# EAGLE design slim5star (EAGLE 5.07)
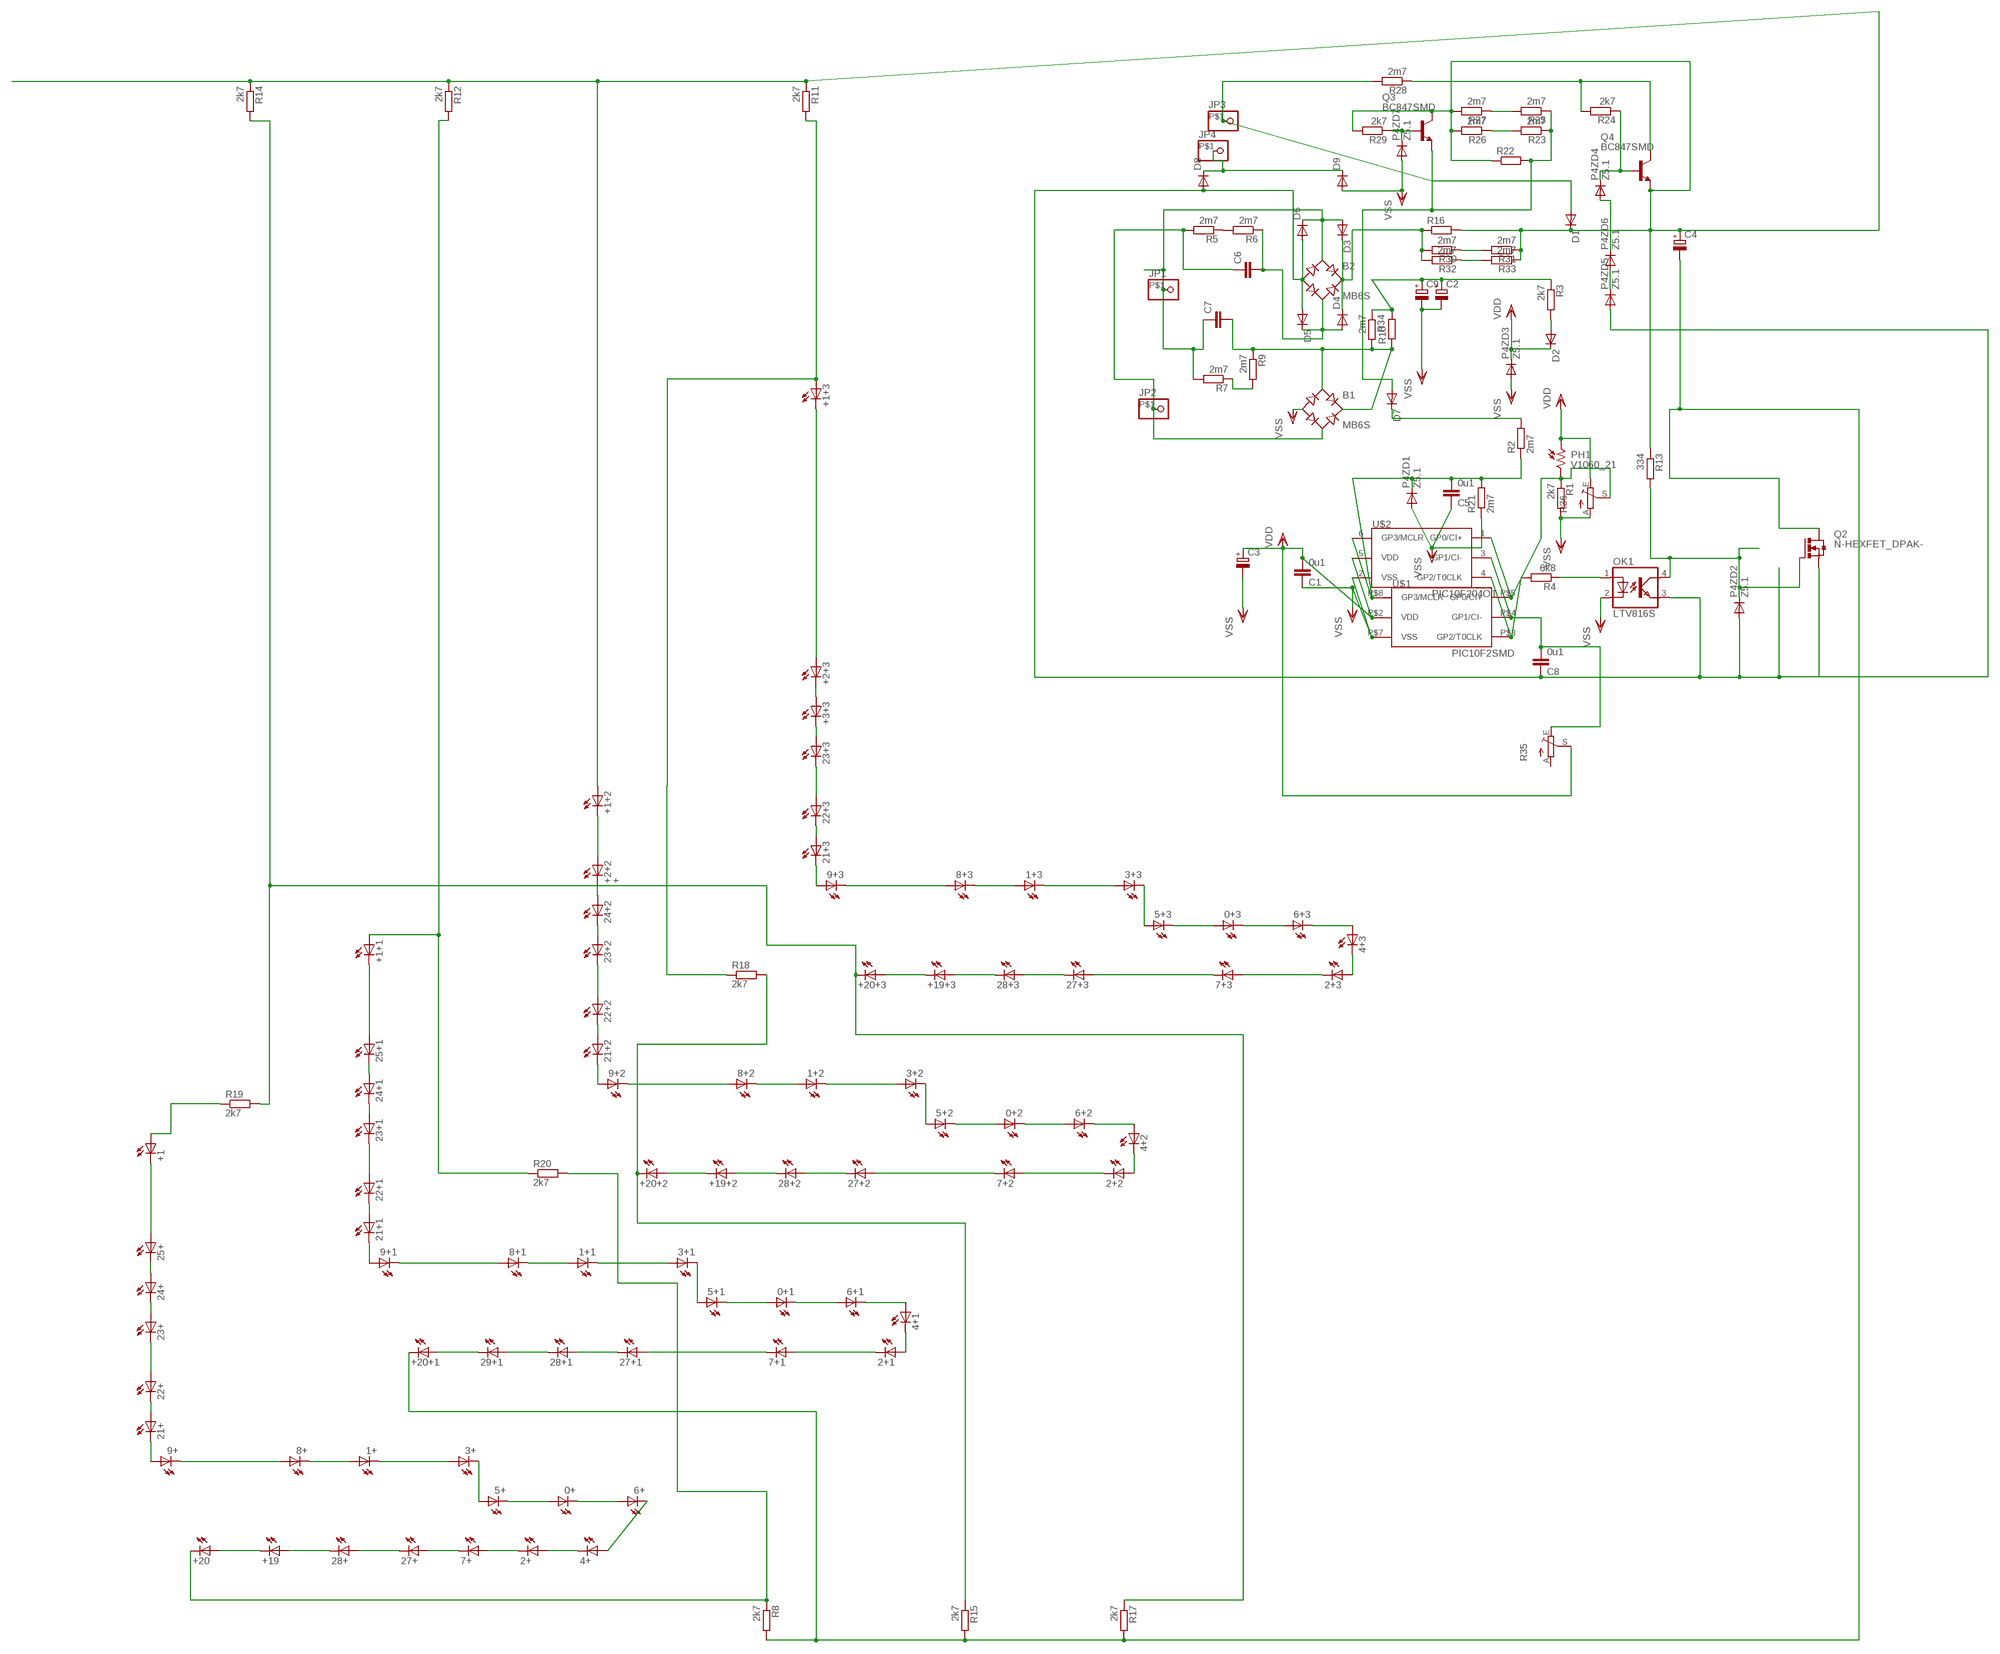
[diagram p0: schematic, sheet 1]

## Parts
0+  LED1210  [1210]
0+1  LED1210  [1210]
0+2  LED1210  [1210]
0+3  LED1210  [1210]
1+  LED1210  [1210]
1+1  LED1210  [1210]
1+2  LED1210  [1210]
1+3  LED1210  [1210]
2+  LED1210  [1210]
2+1  LED1210  [1210]
2+2  LED1210  [1210]
2+3  LED1210  [1210]
3+  LED1210  [1210]
3+1  LED1210  [1210]
3+2  LED1210  [1210]
3+3  LED1210  [1210]
4+  LED1210  [1210]
4+1  LED1210  [1210]
4+2  LED1210  [1210]
4+3  LED1210  [1210]
5+  LED1210  [1210]
5+1  LED1210  [1210]
5+2  LED1210  [1210]
5+3  LED1210  [1210]
6+  LED1210  [1210]
6+1  LED1210  [1210]
6+2  LED1210  [1210]
6+3  LED1210  [1210]
7+  LED1210  [1210]
7+1  LED1210  [1210]
7+2  LED1210  [1210]
7+3  LED1210  [1210]
8+  LED1210  [1210]
8+1  LED1210  [1210]
8+2  LED1210  [1210]
8+3  LED1210  [1210]
9+  LED1210  [1210]
9+1  LED1210  [1210]
9+2  LED1210  [1210]
9+3  LED1210  [1210]
21+  LED1210  [1210]
21+1  LED1210  [1210]
21+2  LED1210  [1210]
21+3  LED1210  [1210]
22+  LED1210  [1210]
22+1  LED1210  [1210]
22+2  LED1210  [1210]
22+3  LED1210  [1210]
23+  LED1210  [1210]
23+1  LED1210  [1210]
23+2  LED1210  [1210]
23+3  LED1210  [1210]
24+  LED1210  [1210]
24+1  LED1210  [1210]
24+2  LED1210  [1210]
25+  LED1210  [1210]
25+1  LED1210  [1210]
27+  LED1210  [1210]
27+1  LED1210  [1210]
27+2  LED1210  [1210]
27+3  LED1210  [1210]
28+  LED1210  [1210]
28+1  LED1210  [1210]
28+2  LED1210  [1210]
28+3  LED1210  [1210]
29+1  LED1210  [1210]
+1  LED1210  [1210]
+1+1  LED1210  [1210]
+1+2  LED1210  [1210]
+1+3  LED1210  [1210]
+2+2  +  LED1210  [1210]
+2+3  LED1210  [1210]
+3+3  LED1210  [1210]
+19  LED1210  [1210]
+19+2  LED1210  [1210]
+19+3  LED1210  [1210]
+20  LED1210  [1210]
+20+1  LED1210  [1210]
+20+2  LED1210  [1210]
+20+3  LED1210  [1210]
B1  MB6S  [SOIC-4]
B2  MB6S  [SOIC-4]
C1  0u1  C-EUC1206  [C1206]
C2  CPOL-EUE2.5-4V  [E2,5RE]
C3  CPOL-EUE  [PANASONIC_E]
C4  CPOL-EUSANYO_SMD_F12  [SANYO-OSCON_SMD_F12]
C5  0u1  C-EUC1206  [C1206]
C6  C-EUSMD200  [SMD200]
C7  C-EUSMD100  [SMD100]
C8  0u1  C-EUC1206  [C1206]
C9  CPOL-EUE  [PANASONIC_E]
D1  DIODE-SMB  [SMB]
D2  DIODE-MINIMELF  [MINIMELF]
D3  DIODE-SMB  [SMB]
D4  DIODE-SMB  [SMB]
D5  DIODE-SMB  [SMB]
D6  DIODE-SMB  [SMB]
D7  DIODE-MINIMELF  [MINIMELF]
D8  DIODE-SMB  [SMB]
D9  DIODE-SMB  [SMB]
JP1  PINHD-1X1SMD  [SMD1X1]
JP2  PINHD-1X1SMD  [SMD1X1]
JP3  PINHD-1X1SMD  [SMD1X1]
JP4  PINHD-1X1SMD  [SMD1X1]
OK1  LTV816S  [SMD4]
P4ZD1  Z5.1  DIODE-MINIMELF  [MINIMELF]
P4ZD2  Z5.1  DIODE-MINIMELF  [MINIMELF]
P4ZD3  Z5.1  DIODE-MINIMELF  [MINIMELF]
P4ZD4  Z5.1  DIODE-MINIMELF  [MINIMELF]
P4ZD5  Z5.1  DIODE-MINIMELF  [MINIMELF]
P4ZD6  Z5.1  DIODE-MINIMELF  [MINIMELF]
P4ZD7  Z5.1  DIODE-MINIMELF  [MINIMELF]
PH1  V1060_21  [TO-5_V10]
Q2  N-HEXFET_DPAK-  [TO252]
Q3  BC847SMD  [SOT23]
Q4  BC847SMD  [SOT23]
R1  2k7  R-EU_R1206  [R1206]
R2  2m7  R-EU_R1206  [R1206]
R3  2k7  R-EU_R1206  [R1206]
R4  6k8  R-EU_R1206  [R1206]
R5  2m7  R-EU_R1210  [R1210]
R6  2m7  R-EU_R1210  [R1210]
R7  2m7  R-EU_R1210  [R1210]
R8  2k7  R-EU_R0402  [R0402]
R9  2m7  R-EU_R1210  [R1210]
R10  R-EU_SMD15  [SMDCARB15]
R11  2k7  R-EU_R0402  [R0402]
R12  2k7  R-EU_R0402  [R0402]
R13  334  R-EU_R1206  [R1206]
R14  2k7  R-EU_R0402  [R0402]
R15  2k7  R-EU_R0402  [R0402]
R16  R-EU_SMD15  [SMDCARB15]
R17  2k7  R-EU_R0402  [R0402]
R18  2k7  R-EU_R0402  [R0402]
R19  2k7  R-EU_R0402  [R0402]
R20  2k7  R-EU_R0402  [R0402]
R21  2m7  R-EU_R1206  [R1206]
R22  R-EU_SMD15  [SMDCARB15]
R23  2m7  R-EU_R1210  [R1210]
R24  2k7  R-EU_R1206  [R1206]
R25  2m7  R-EU_R1210  [R1210]
R26  2m7  R-EU_R1210  [R1210]
R27  2m7  R-EU_R1210  [R1210]
R28  2m7  R-EU_R1210  [R1210]
R29  2k7  R-EU_R1206  [R1206]
R30  2m7  R-EU_R1210  [R1210]
R31  2m7  R-EU_R1210  [R1210]
R32  2m7  R-EU_R1210  [R1210]
R33  2m7  R-EU_R1210  [R1210]
R34  2m7  R-EU_R1210  [R1210]
R35  TRIM_EU-LI15  [LI15]
R36  TRIM_EU-LI15  [LI15]
U$1  PIC10F2SMD  [DIL8SMD]
U$2  PIC10F204OT  [SOT23-6]

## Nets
AC1: B1.~2(AC2) C6.P$1 JP2.P$1 R5.2
AC2: B2.~1(AC1) C7.P$1 D3.A D6.C JP1.P$1 R7.2
CBIG: B2.~2(AC2) C6.P$2 D4.A D5.C R6.1
CSMALL: D7.A Q3.2(E) R22.P$2 R23.1 R25.1
D+: +1+2.P$1(A) C4.+ D1.C Q3.3(C) Q4.2(E) R11.1 R12.1 R13.1 R14.1 R16.P$2 R22.P$1 R26.2 R27.2 R29.2 R31.1 R33.1
MINUS: +20+1.P$2(C) C4.- Q2.3(D) R8.2 R15.2 R17.2
N$1: +1+3.P$1(A) R11.2 R18.1
N$2: +1+1.P$1(A) R12.2 R20.1
N$4: +1.P$1(A) R19.1
N$5: D7.C R2.2
N$6: 8+.P$1(A) 9+.P$2(C)
N$7: +19.P$2(C) +20.P$1(A)
N$8: 28+.P$2(C) +19.P$1(A)
N$9: 27+.P$2(C) 28+.P$1(A)
N$10: 29+1.P$2(C) +20+1.P$1(A)
N$11: 28+1.P$2(C) 29+1.P$1(A)
N$12: 2+.P$2(C) 7+.P$1(A)
N$13: 7+.P$2(C) 27+.P$1(A)
N$14: 2+.P$1(A) 4+.P$2(C)
N$15: 4+.P$1(A) 6+.P$2(C)
N$16: 0+.P$2(C) 6+.P$1(A)
N$17: 0+.P$1(A) 5+.P$2(C)
N$18: 3+.P$2(C) 5+.P$1(A)
N$19: 1+.P$2(C) 3+.P$1(A)
N$20: 1+.P$1(A) 8+.P$2(C)
N$21: 27+1.P$2(C) 28+1.P$1(A)
N$22: 2+1.P$1(A) 4+1.P$2(C)
N$23: 9+.P$1(A) 21+.P$2(C)
N$24: 21+.P$1(A) 22+.P$2(C)
N$25: 22+.P$1(A) 23+.P$2(C)
N$26: 24+.P$1(A) 25+.P$2(C)
N$27: 25+.P$1(A) +1.P$2(C)
N$28: 23+.P$1(A) 24+.P$2(C)
N$29: 4+1.P$1(A) 6+1.P$2(C)
N$30: 0+1.P$2(C) 6+1.P$1(A)
N$31: 0+1.P$1(A) 5+1.P$2(C)
N$32: 3+1.P$2(C) 5+1.P$1(A)
N$33: 1+1.P$2(C) 3+1.P$1(A)
N$34: 1+1.P$1(A) 8+1.P$2(C)
N$35: 9+1.P$1(A) 21+1.P$2(C)
N$36: 21+1.P$1(A) 22+1.P$2(C)
N$37: 22+1.P$1(A) 23+1.P$2(C)
N$38: 25+1.P$1(A) +1+1.P$2(C)
N$39: 24+1.P$1(A) 25+1.P$2(C)
N$40: 23+1.P$1(A) 24+1.P$2(C)
N$41: 2+1.P$2(C) 7+1.P$1(A)
N$42: 7+1.P$2(C) 27+1.P$1(A)
N$43: 8+1.P$1(A) 9+1.P$2(C)
N$45: +20+3.P$2(C) R14.2 R17.1 R19.2
N$46: +19+2.P$2(C) +20+2.P$1(A)
N$47: 28+2.P$2(C) +19+2.P$1(A)
N$48: 27+2.P$2(C) 28+2.P$1(A)
N$49: 2+2.P$1(A) 4+2.P$2(C)
N$50: 4+2.P$1(A) 6+2.P$2(C)
N$51: 0+2.P$2(C) 6+2.P$1(A)
N$52: 0+2.P$1(A) 5+2.P$2(C)
N$53: 3+2.P$2(C) 5+2.P$1(A)
N$54: 1+2.P$2(C) 3+2.P$1(A)
N$55: 1+2.P$1(A) 8+2.P$2(C)
N$56: 9+2.P$1(A) 21+2.P$2(C)
N$57: 21+2.P$1(A) 22+2.P$2(C)
N$58: 22+2.P$1(A) 23+2.P$2(C)
N$59: +1+2.P$2(C) +2+2.P$1(A)
N$60: 24+2.P$1(A) +2+2.P$2(C)
N$61: 23+2.P$1(A) 24+2.P$2(C)
N$62: 2+2.P$2(C) 7+2.P$1(A)
N$63: 7+2.P$2(C) 27+2.P$1(A)
N$64: 8+2.P$1(A) 9+2.P$2(C)
N$65: +20+2.P$2(C) R15.1 R18.2
N$66: +20.P$2(C) R8.1 R20.2
N$67: +19+3.P$2(C) +20+3.P$1(A)
N$68: 28+3.P$2(C) +19+3.P$1(A)
N$69: 27+3.P$2(C) 28+3.P$1(A)
N$70: 2+3.P$1(A) 4+3.P$2(C)
N$71: 4+3.P$1(A) 6+3.P$2(C)
N$72: 0+3.P$2(C) 6+3.P$1(A)
N$73: 0+3.P$1(A) 5+3.P$2(C)
N$74: 3+3.P$2(C) 5+3.P$1(A)
N$75: 1+3.P$2(C) 3+3.P$1(A)
N$76: 1+3.P$1(A) 8+3.P$2(C)
N$77: 9+3.P$1(A) 21+3.P$2(C)
N$78: 21+3.P$1(A) 22+3.P$2(C)
N$79: 22+3.P$1(A) 23+3.P$2(C)
N$80: +1+3.P$2(C) +2+3.P$1(A)
N$81: +2+3.P$2(C) +3+3.P$1(A)
N$82: 23+3.P$1(A) +3+3.P$2(C)
N$83: 2+3.P$2(C) 7+3.P$1(A)
N$84: 7+3.P$2(C) 27+3.P$1(A)
N$85: 8+3.P$1(A) 9+3.P$2(C)
N$86: C5.2 P4ZD1.C R2.1 R21.2 U$1.P$8(GP3/MCLR) U$2.6(GP3/MCLR)
N$87: OK1.1(A) R4.1
N$88: PH1.2 R1.1 R36.S U$1.P$5(GP0/CI+) U$2.1(GP0/CI+)
N$89: R5.1 R6.2
N$90: R7.1 R9.2
N$91: B2.+ D3.C D4.C R16.P$1 R30.2 R32.2
N$92: D2.A R3.2
N$93: B2.- C8.1 D5.A D6.A D8.A OK1.3(EMIT) P4ZD2.A P4ZD5.A Q2.2(S)
N$94: OK1.4(COL) P4ZD2.C Q2.1(G) R13.2
N$95: R4.2 U$1.P$3(GP2/T0CLK) U$2.4(GP2/T0CLK)
N$96: Q4.3(C) R24.2 R28.1
N$97: P4ZD4.C Q4.1(B) R24.1
N$98: D1.A JP3.P$1 R28.2
N$99: R23.2 R26.1
N$100: R25.2 R27.1
N$101: C2.+ C9.+ R3.1 R10.P$2 R34.1
N$102: C8.2 R35.E U$1.P$4(GP1/CI-) U$2.3(GP1/CI-)
N$103: P4ZD5.C P4ZD6.A
N$104: P4ZD7.C Q3.1(B) R29.1
N$105: P4ZD4.A P4ZD6.C
N$106: D8.C D9.C JP4.P$1
N$107: R30.1 R31.2
N$108: R32.1 R33.2
RECDR+: B1.+ B1.~1(AC1) C7.P$2 R9.1 R10.P$1 R34.2
VDD: C1.2 C3.+ D2.C P4ZD3.C PH1.1 R35.S R36.E U$1.P$2(VDD) U$2.5(VDD)
VSS: B1.- C1.1 C2.- C3.- C5.1 C9.- D9.A OK1.2(C) P4ZD1.A P4ZD3.A P4ZD7.A R1.2 R21.1 R36.A U$1.P$7(VSS) U$2.2(VSS)
Unconnected: R35.A

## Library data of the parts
0+ 0+1-0+3 1+ 1+1-1+3 2+ 2+1-2+3 3+ 3+1-3+3 4+ 4+1-4+3 5+ 5+1-5+3 6+ 6+1-6+3 7+ 7+1-7+3 8+ 8+1-8+3 9+ 9+1-9+3 21+ 21+1-21+3 22+ 22+1-22+3 23+ 23+1-23+3 24+ 24+1 24+2 25+ 25+1 27+ 27+1-27+3 28+ 28+1-28+3 29+1 +1 +1+1-+1+3 +2+2 +2+3 +3+3 +19 +19+2 +19+3 +20 +20+1-+20+3 = led(2):LED: LED
B1 B2 = rectifier:MB*S: Bridge Rectifier Source: http://www.fairchildsemi.com/ds/MB/MB6S.pdf
C1 C5-C8 = rcl:C-EU: CAPACITOR, European symbol
C2-C4 C9 = rcl-2:CPOL-EU: POLARIZED CAPACITOR, European symbol
D1-D9 P4ZD1-P4ZD7 = diode:DIODE-: DIODE
JP1-JP4 = pinhead:PINHD-1X1: PIN HEADER
OK1 = optocoupler:LTV816: OPTO COUPLER Source: LITEON, LTV816.pdf
PH1 = photo-elements:?1060*: Sensor Street Light control
Q2 = transistor-power:N-HEXFET_?-*: HEXFET® Power MOSFET
Q3 Q4 = transistor-npn:BC847*: NPN Transistor
R1-R9 R11-R15 R17-R21 R23-R34 = rcl-2:R-EU_: RESISTOR, European symbol
R10 R16 R22 = rcl:R-EU_: RESISTOR, European symbol
R35 R36 = pot:TRIM_EU-: POTENTIOMETER
U$1 U$2 = microchip-5:PIC10F2*: uPC nW 0,25/0,5k Program Flash memory Comparator

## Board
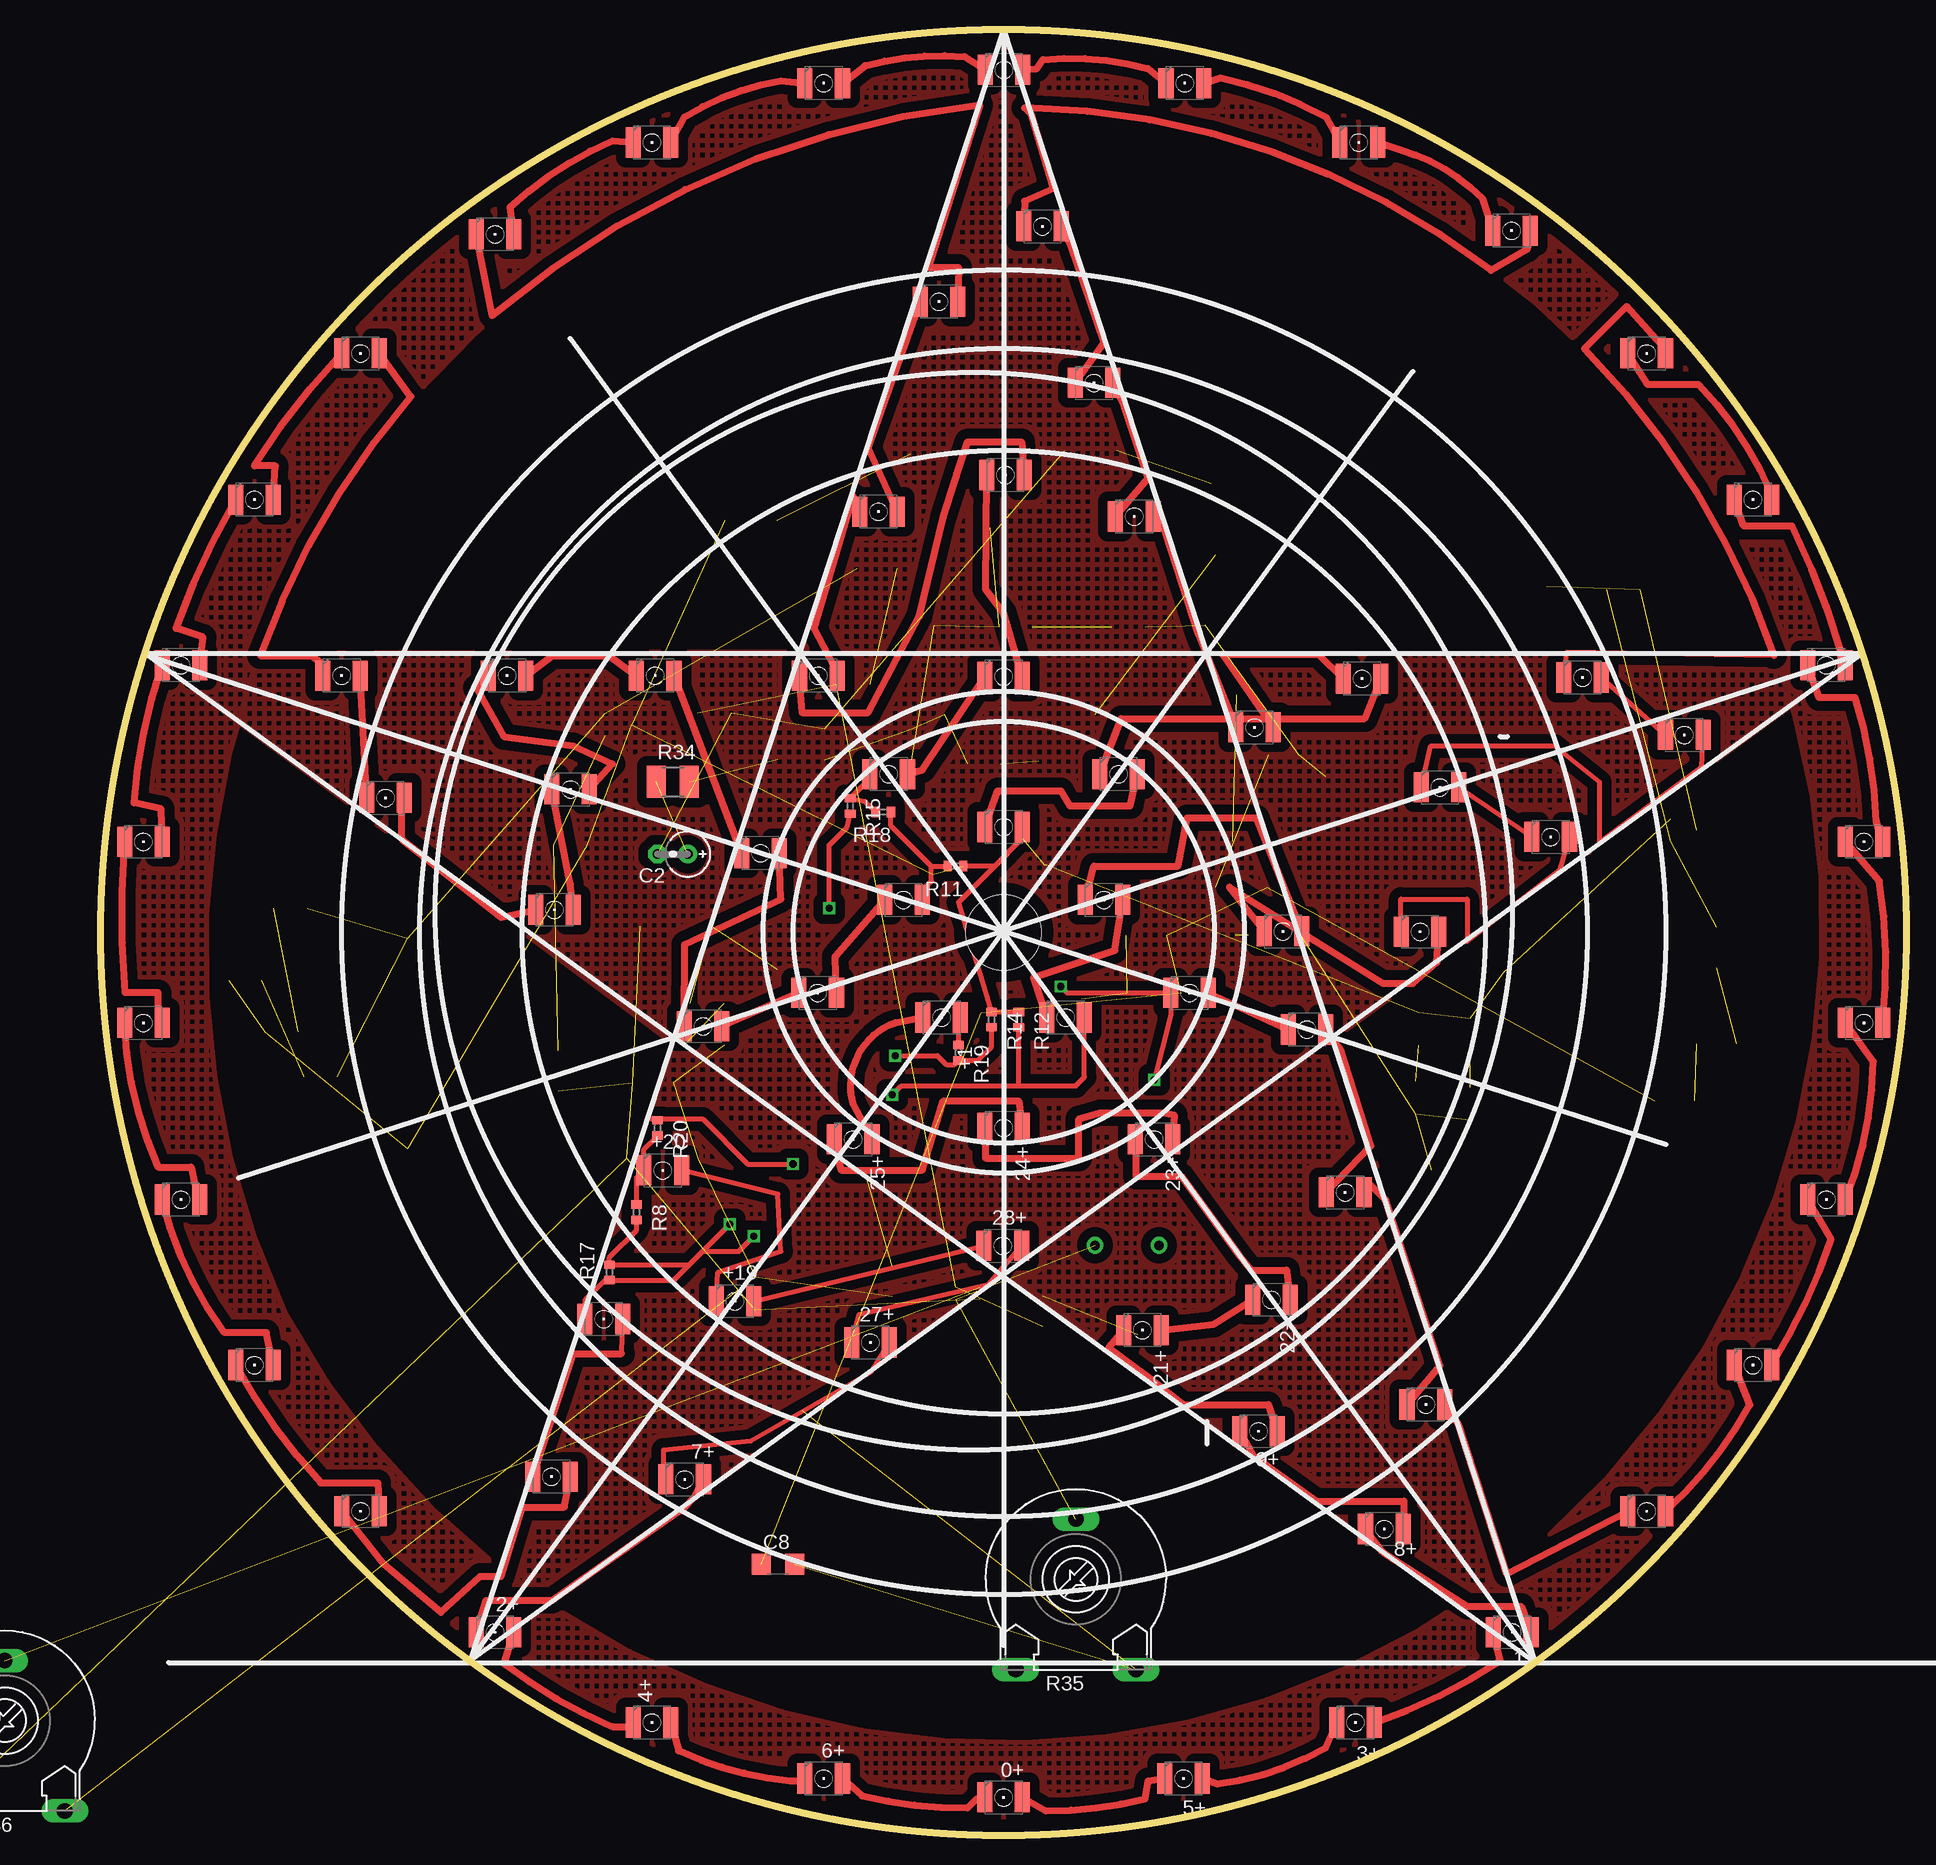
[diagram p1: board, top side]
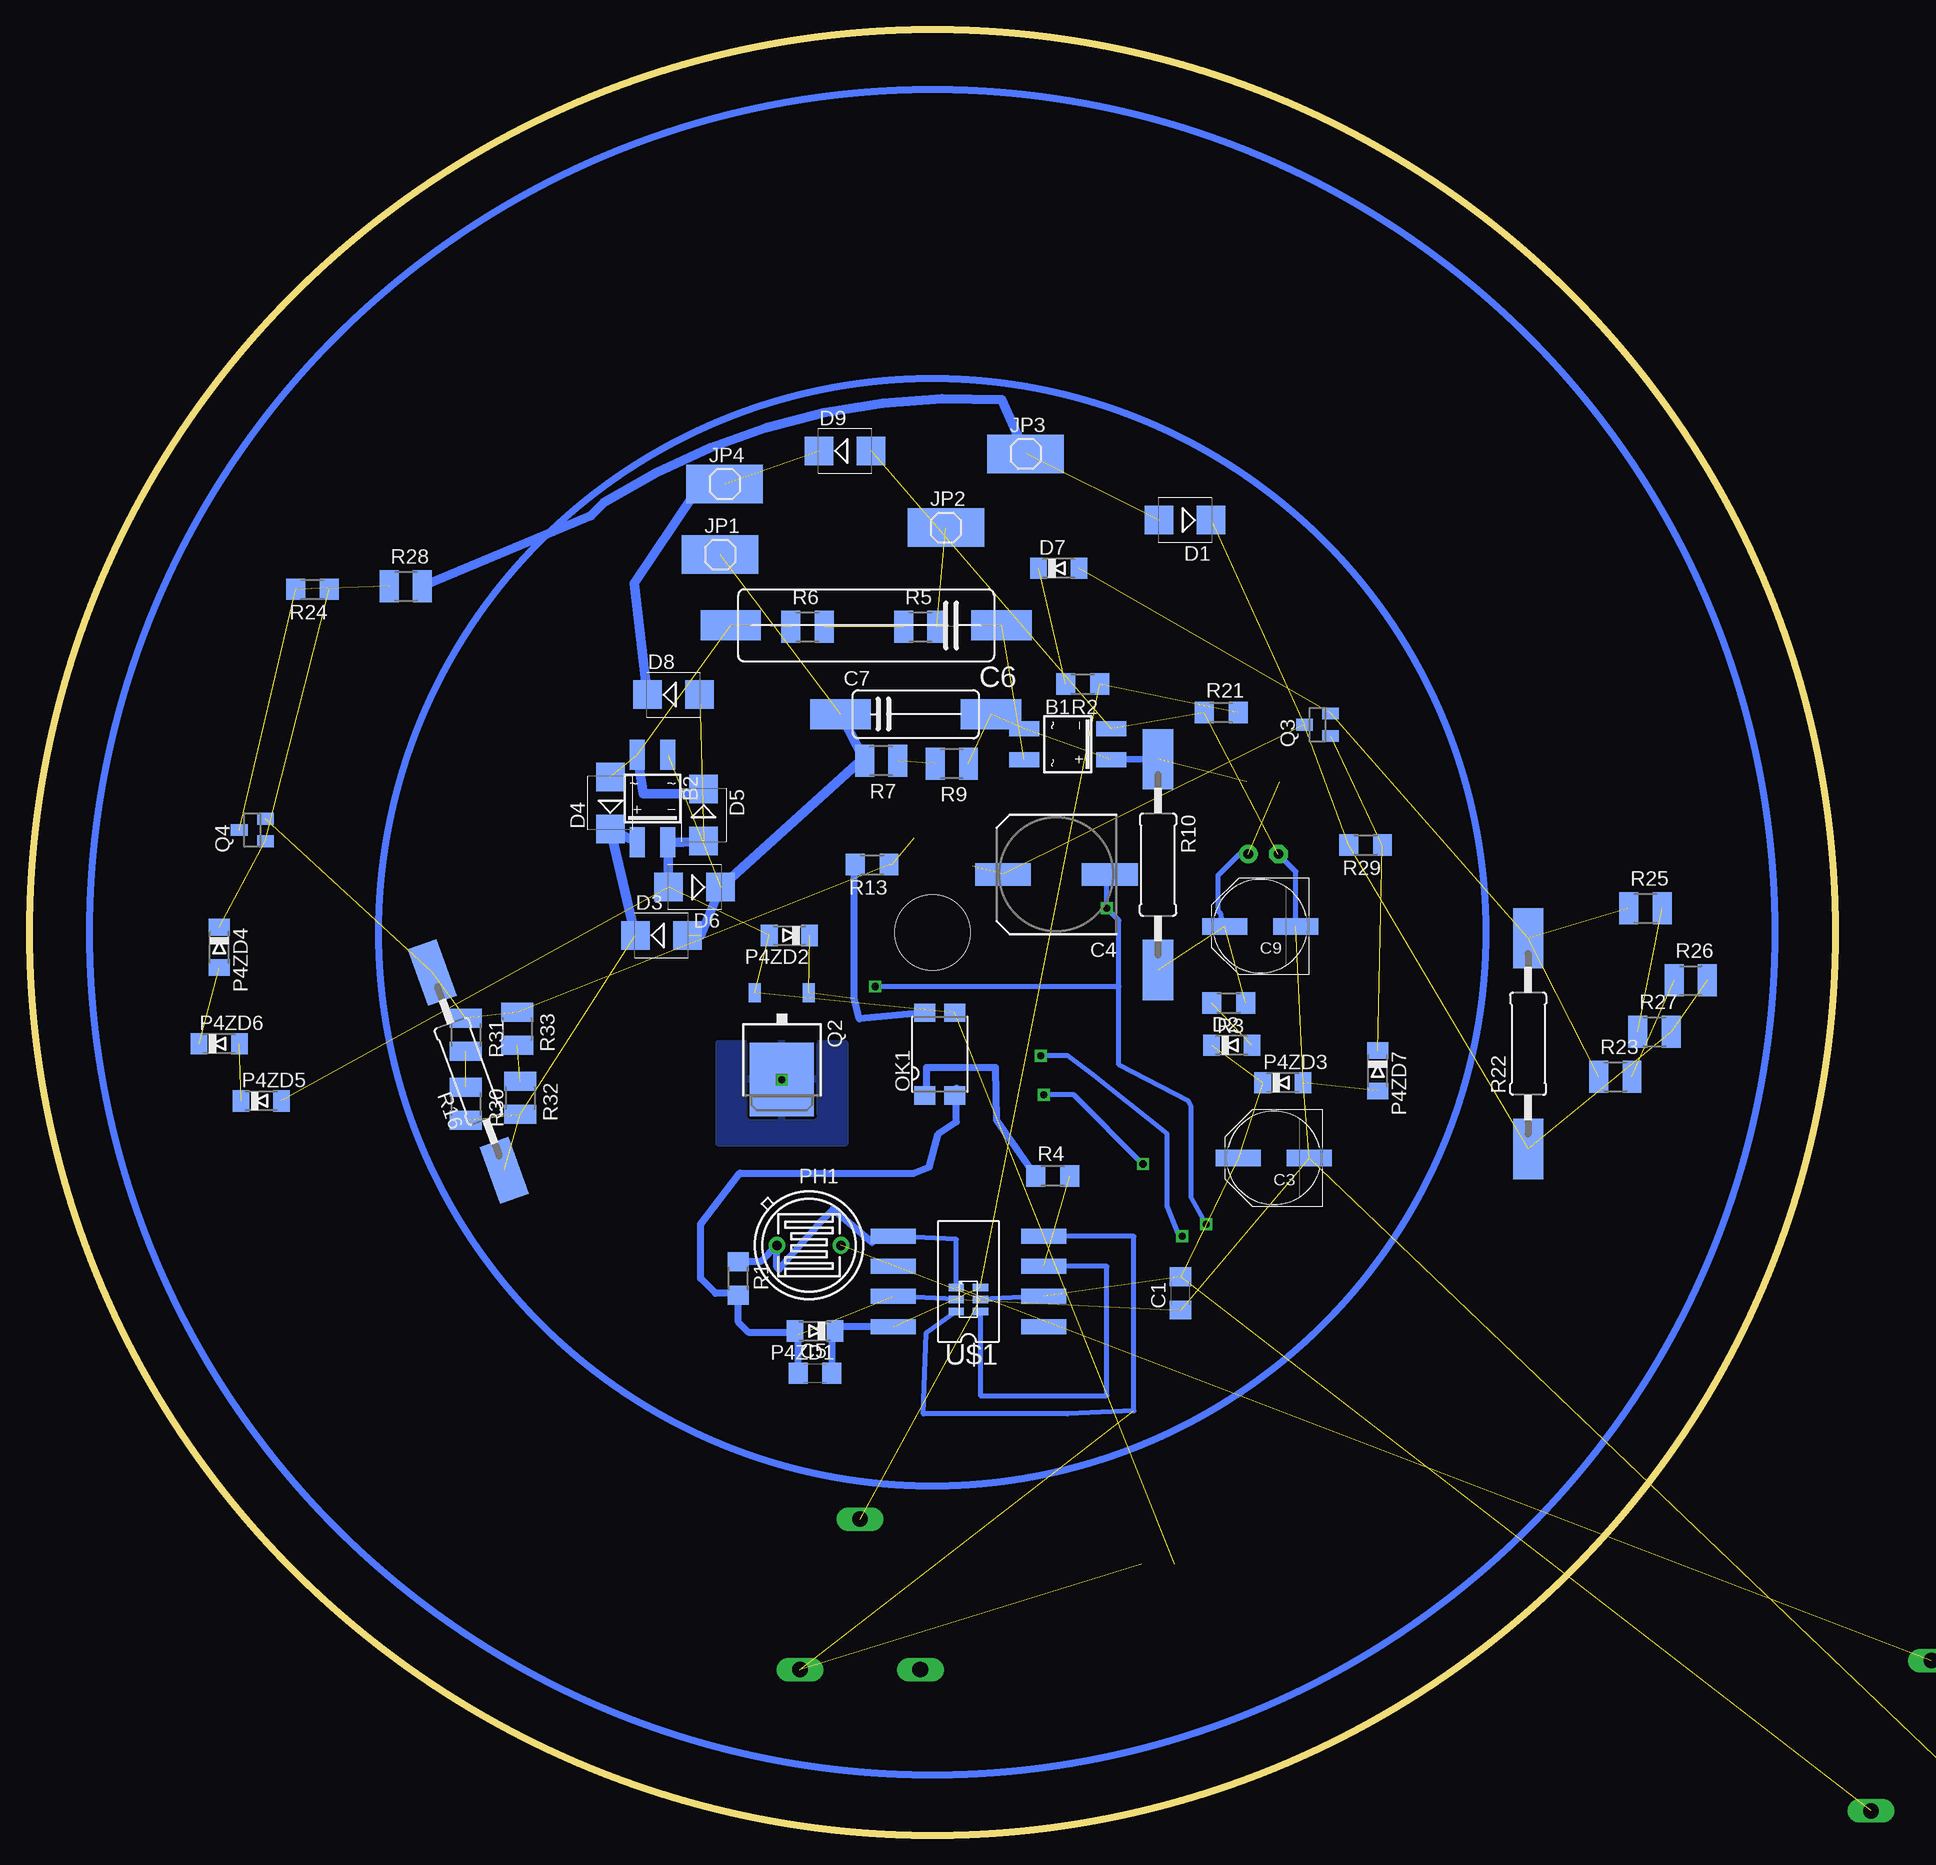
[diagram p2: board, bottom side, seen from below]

Size 152.4 x 152.4 mm. Coordinates in mm from the lower left corner, seen from the top.
Outline: circle at 76.2,76.2 radius 76.2
Copper layers (1*16): Top 0.035mm / dielectric 1.5mm / Bottom 0.035mm
Design rules "default": minimum track width 10mil, minimum drill 24mil, track to track 8mil, track to pad 8mil, pad to pad 8mil, via to via 8mil, smd to smd 8mil, copper to edge 40mil, drill to drill 8mil, minimum pad ring 10mil, minimum via ring 8mil, stop-mask expansion 4mil, vias tented up to drill 0mil, thermal gap 10mil
Holes 6.35 mm at 76.2,76.2

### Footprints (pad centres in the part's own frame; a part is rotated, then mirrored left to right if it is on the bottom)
1210 = smd 1.27 x 2.54: P$1 1.587,0; P$2 -1.587,0
SOIC-4 = smd 1.27 x 2.54: + 1.3,3.685; - -1.3,3.685; ~1 -1.3,-3.685; ~2 1.3,-3.685
C1206 = smd 1.6 x 1.8: 1 -1.4,0; 2 1.4,0
E2,5RE = drill 0.813 pad 1.575 round: + -1.27,0 | drill 0.813 pad 1.575 octagon: - 1.27,0
PANASONIC_E = smd 3.8 x 1.4: + 3,0; - -3,0
SANYO-OSCON_SMD_F12 = smd 4.7 x 1.9: + 4.5,0; - -4.5,0
SMD200 = smd 5.08 x 2.54: P$1 -10.16,0; P$2 12.7,0
SMD100 = smd 5.08 x 2.54: P$1 -6.35,0; P$2 6.35,0
SMB = smd 2.4 x 2.4: A 2.2,0; C -2.2,0
MINIMELF = smd 1.4 x 1.8: A 1.7,0; C -1.7,0
SMD1X1 = smd 6.452 x 3.251: P$1 0,0
SMD4 = smd 1.78 x 1.55: 1 -1.27,-3.5; 2 1.27,-3.5; 3 1.27,3.5; 4 -1.27,3.5
TO-5_V10 = drill 0.8 pad 1.4 round: 1 -2.7,0; 2 2.7,0
TO252 = smd 1 x 1.6: 1 -2.28,-3.53; 2 2.28,-3.53 | smd 5.4 x 6.2: 3 0,3.77
SOT23 = smd 1 x 1.4: 1 -0.95,-1.1; 2 0.95,-1.1; 3 0,1.1
R1206 = smd 1.6 x 1.803: 1 -1.422,0; 2 1.422,0
R1210 = smd 1.6 x 2.7: 1 -1.4,0; 2 1.4,0
R0402 = smd 0.7 x 0.9: 1 -0.65,0; 2 0.65,0
SMDCARB15 = smd 5.08 x 2.54: P$1 -8.89,0; P$2 8.89,0
LI15 = drill 1.321 long: A -5.08,-7.62; E 5.08,-7.62; S 0,5.08
DIL8SMD = smd 1.27 x 3.81: P$1 -3.81,-6.35; P$2 -1.27,-6.35; P$3 1.27,-6.35; P$4 3.81,-6.35; P$5 3.81,6.35; P$6 1.27,6.35; P$7 -1.27,6.35; P$8 -3.81,6.35
SOT23-6 = smd 0.635 x 1.27: 1 -1.016,-1.016; 2 0,-1.016; 3 1.016,-1.016; 4 1.016,1.016; 5 0,1.016; 6 -1.016,1.016

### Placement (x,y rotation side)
0+  76.2,3.17 0 top
0+1  148.82,83.85 0 top
0+2  61.01,147.88 0 top
0+3  12.95,112.73 0 top
1+  119.13,17.12 0 top
1+1  130.48,125.07 0 top
1+2  106.17,142.88 0 top
1+3  24.03,87.55 0 top
2+  33.27,17.12 0 top
2+1  139.45,39.67 0 top
2+2  70.74,129.44 0 top
2+3  3.58,68.55 0 top
3+  105.89,9.5 0 top
3+1  139.45,112.73 0 top
3+2  91.49,147.88 0 top
3+3  20.32,97.87 0 top
4+  46.51,9.5 0 top
4+1  145.64,53.64 0 top
4+2  33.27,135.13 0 top
4+3  3.58,83.85 0 top
5+  91.39,4.78 0 top
5+1  145.64,98.76 0 top
5+2  76.23,149 0 top
5+3  21.92,125.07 0 top
6+  61.01,4.78 0 top
6+1  148.82,68.55 0 top
6+2  46.51,142.88 0 top
6+3  6.76,98.76 0 top
7+  49.28,30.02 0 top
7+1  130.48,27.33 0 top
7+2  65.63,111.71 0 top
7+3  6.76,53.64 0 top
8+  108.33,25.83 0 top
8+1  125.07,97.71 0 top
8+2  119.08,135.43 0 top
8+3  38.28,78.11 0 top
9+  97.71,34.09 0 top
9+1  133.65,92.86 0 top
9+2  79.48,135.79 0 top
9+3  39.65,88.27 0 top
21+  87.91,42.62 0 top
21+1  113.03,88.44 0 top
21+2  83.82,122.58 0 top
21+3  34.29,97.87 0 top
22+  98.81,45.19 0 top
22+1  122.38,84.25 0 top
22+2  87.22,111.3 0 top
22+3  46.79,97.87 0 top
23+  88.9,58.72 0 top
23+1  111.35,76.25 0 top
23+2  97.38,93.5 0 top
23+3  55.68,82.88 0 top
24+  76.2,59.69 0 top
24+1  99.77,76.28 0 top
24+2  106.45,97.61 0 top
25+  63.5,58.72 0 top
25+1  84.66,78.94 0 top
27+  64.95,41.58 0 top
27+1  111.84,36.35 0 top
27+2  60.55,97.87 0 top
27+3  12.95,39.67 0 top
28+  76.12,49.73 0 top
28+1  105.03,54.25 0 top
28+2  76.35,114.81 0 top
28+3  21.92,27.33 0 top
29+1  101.8,68 0 top
+1  70.97,69.01 0 top
+1+1  81.43,69.01 0 top
+1+2  76.2,85.09 0 top
+1+3  67.74,78.94 0 top
+2+2  85.9,89.56 0 top
+2+3  60.5,71.09 0 top
+3+3  50.83,68.28 0 top
+19  53.52,45.06 0 top
+19+2  76.2,97.79 0 top
+19+3  38.02,30.25 0 top
+20  47.42,56.11 0 top
+20+1  91.9,71.09 0 top
+20+2  66.5,89.56 0 top
+20+3  42.44,43.56 0 top
B1  64.77,92.08 270 bottom
B2  99.82,87.5 180 bottom
C1  55.24,45.72 90 bottom
C2  48.26,82.8 180 top
C3  47.37,57.15 180 bottom
C4  65.73,81.09 180 bottom
C5  86.11,38.99 0 bottom
C6  80.52,102.11 180 bottom
C7  77.6,94.61 0 bottom
C8  57.15,22.86 0 top
C9  48.51,76.71 180 bottom
D1  54.86,111 180 bottom
D2  50.93,66.67 0 bottom
D3  99.06,75.95 0 bottom
D4  103.38,87.12 90 bottom
D5  95.5,86.11 270 bottom
D6  96.27,80.01 180 bottom
D7  65.53,106.93 0 bottom
D8  98.04,96.27 0 bottom
D9  83.57,116.84 0 bottom
JP1  94.11,108.08 0 bottom
JP2  75.06,110.36 0 bottom
JP3  68.33,116.59 0 bottom
JP4  93.73,114.05 0 bottom
OK1  75.56,65.91 0 bottom
P4ZD1  86.11,42.55 180 bottom
P4ZD2  88.27,75.95 180 bottom
P4ZD3  46.61,63.5 0 bottom
P4ZD4  136.4,74.93 270 bottom
P4ZD5  132.84,61.98 0 bottom
P4ZD6  136.4,66.8 0 bottom
P4ZD7  38.61,64.52 270 bottom
PH1  86.61,49.78 180 bottom
Q2  88.9,67.56 180 bottom
Q3  43.69,93.73 90 bottom
Q4  133.6,84.84 90 bottom
R1  92.58,46.99 270 bottom
R2  63.5,97.16 180 bottom
R3  51.18,70.23 180 bottom
R4  66.04,55.63 0 bottom
R5  77.22,101.98 0 bottom
R6  86.74,101.98 0 bottom
R7  80.52,90.68 180 bottom
R8  45.21,52.58 270 top
R9  74.55,90.42 180 bottom
R10  57.15,81.92 270 bottom
R11  72.14,81.79 180 top
R12  77.47,68.83 270 top
R13  81.28,81.92 180 bottom
R14  75.18,68.83 270 top
R15  63.25,86.87 270 top
R16  115.37,64.46 110 bottom
R17  42.93,47.5 90 top
R18  66.04,86.36 180 top
R19  72.39,66.04 270 top
R20  46.99,59.69 270 top
R21  51.82,94.74 0 bottom
R22  25.91,66.8 90 bottom
R23  18.54,64.01 0 bottom
R24  128.52,105.16 180 bottom
R25  16,78.23 0 bottom
R26  12.19,72.14 0 bottom
R27  15.24,67.82 0 bottom
R28  120.65,105.41 0 bottom
R29  39.62,83.57 180 bottom
R30  115.57,61.72 270 bottom
R31  115.57,67.56 270 bottom
R32  111,62.23 270 bottom
R33  111.25,68.07 270 bottom
R34  48.26,88.9 0 top
R35  82.3,21.59 0 top
R36  not placed on the board
U$1  73.15,46.74 90 bottom
U$2  73.15,45.21 270 bottom

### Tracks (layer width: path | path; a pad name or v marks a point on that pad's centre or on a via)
AC1  (3 unrouted)
AC2  (3 unrouted)
  Bottom 0.813: C7.P$1 R7.2 82.55,90.42 D6.C 95.76,75.95
CBIG  (3 unrouted)
  Bottom 0.813: D5.C 97.03,87.88 100.58,87.88 B2.~2
CSMALL  (4 unrouted)
D+  (13 unrouted)
  Top 0.406: 75.44,81.79 R11.1 | +1+2.P$1 77.79,84.14 75.44,81.79 | 75.44,81.79 72.39,78.74 R14.1 R12.1
  Bottom 0.61: 79.5,81.79 79.63,81.92
MINUS  (via drill 0.6)
  Top 0.406: R15.2 62.99,85.09 61.47,83.57 v61.47,78.23 | v53.09,51.56 49.67,48.15 R17.2 42.93,48.77 45.21,51.05 R8.2 | v81.03,71.63 81.56,71.09 +20+1.P$2 90.31,69.23 v88.9,63.75
  Bottom 0.406: C4.- 61.47,80.85 v61.47,78.23 60.45,77.22 60.45,71.63 | v53.09,51.56 54.36,53.85 54.36,61.47 54.61,61.98 60.45,65.02 60.45,71.63 | 60.45,71.63 v81.03,71.63 | v88.9,63.75 Q2.3
  pour Bottom (isolate 0.813): 83.57,66.8 94.23,66.8 94.23,58.42 83.57,58.42
N$1
  Top 0.406: R18.1 66.69,85.2 70.1,81.79 | 70.1,81.79 R11.2 | 70.1,81.79 70.1,80.52 69.34,79.76 69.34,78.96 +1+3.P$1
N$2  (via drill 0.6)
  Top 0.406: +1+1.P$1 83.02,63.97 82.3,63.25 77.47,63.25 | v66.8,62.48 67.56,63.25 74.68,63.25 77.47,63.25 | v58.42,56.64 54.61,56.64 50.8,60.45 46.88,60.45 | 46.88,60.45 46.48,60.45 | R20.1 46.88,60.45 | 77.47,63.25 R12.2
  Bottom 0.406: v66.8,62.48 64.26,62.48 v58.42,56.64
N$3
  pour Top (isolate 0.813, hatched): 48.31,66.78 31.24,14.66 76.33,47.45 120.95,14.66 104.27,67.36 148.74,99.77 93.29,99.72 76.2,152.4 59.18,99.87 3.76,99.75
N$4
  Top 0.406: R19.1 72.39,68.85 +1.P$1
N$5  (1 unrouted)
N$6
  Top 0.61: 8+.P$1 109.98,28.19 102.62,28.19 97.28,32 9+.P$2
N$7
  Top 0.406: +19.P$2 52.07,47.5 57.4,49.28 57.15,54.1 +20.P$1
N$8
  Top 0.406: +19.P$1 28+.P$2
N$9
  Top 0.406: 28+.P$1 74.93,46.48 64.01,43.94 27+.P$2
N$10
  Top 0.61: +20+1.P$1 29+1.P$2
N$11
  Top 0.61: 28+1.P$2 107.19,58.17 104.65,66.29 29+1.P$1
N$12
  Top 0.61: 7+.P$1 50.1,28.51 49.28,27.69 38.1,19.81 32.51,19.81 2+.P$2
N$13
  Top 0.406: 27+.P$1 65.02,39.12 54.86,33.27 47.5,32.51 47.5,30.99 47.75,30.99 48.01,30.48 7+.P$2
N$14
  Top 0.61: 2+.P$1 34.04,14.48 arc14 43.18,9.14 44.92,9.14 4+.P$2
N$15
  Top 0.61: 4+.P$1 48.77,7.11 arc19 58.17,4.57 59.22,4.57 6+.P$2
N$16
  Top 0.61: 6+.P$1 64.26,3.3 arc13 73.15,2.29 73.91,3.05 0+.P$2
N$17
  Top 0.61: 0+.P$1 79.76,2.03 arc13 88.14,3.05 88.39,4.57 5+.P$2
N$18
  Top 0.61: 5+.P$1 94.23,4.32 arc23 103.38,7.37 3+.P$2
N$19
  Top 0.61: 3+.P$1 arc16 118.11,14.73 1+.P$2
N$20
  Top 0.61: 1+.P$1 119.89,19.3 115.32,19.3 108.2,23.88 8+.P$2
N$21
  Top 0.61: 27+1.P$2 113.03,39.62 108.46,53.59 106.78,55.27 28+1.P$1
N$22
  Top 0.61: 4+1.P$2 146.05,50.29 arc-13 2+1.P$1
N$23
  Top 0.61: 9+.P$1 98.54,36.34 91.4,36.34 88.1,38.88 88.14,38.86 85.09,41.15 21+.P$2
N$24
  Top 0.61: 21+.P$1 93.94,43.13 22+.P$2
N$25
  Top 0.61: 22+.P$1 100.08,47.5 100.08,47.69 97.09,47.69 96.01,49.02 91.19,55.63 87.38,55.63 87.38,58.81 23+.P$2
N$26
  Top 0.61: 25+.P$2 62.48,56.13 69.34,56.13 71.12,61.98 77.47,61.98 24+.P$1
N$27
  Top 0.61: +1.P$2 67.06,68.58 arc86 63.5,61.72 25+.P$1
N$28
  Top 0.61: 23+.P$1 90.59,60.8 89.66,60.96 84.33,60.96 82.55,60.45 82.55,57.15 74.68,57.15 74.68,58.74 24+.P$2
N$29
  Top 0.61: 6+1.P$2 149.61,65.28 arc-22 4+1.P$1
N$30
  Top 0.61: 0+1.P$2 150.11,80.52 arc-15 6+1.P$1
N$31
  Top 0.61: 5+1.P$2 145.03,96.01 148.08,96.01 arc-15 149.86,85.6 0+1.P$1
N$32
  Top 0.61: 3+1.P$2 138.68,110.49 142.75,110.49 arc-10 147.07,99.31 5+1.P$1
N$33
  Top 0.61: 1+1.P$2 130.56,122.43 134.87,122.43 arc-21 140.97,113.28 3+1.P$1
N$34
  Top 0.406: 8+1.P$2 123.7,99.82 141.22,99.57
  Top 0.61: 141.22,99.57 arc25 125.22,125.48 128.78,129.03 131.32,126.24 131.83,125.73 1+1.P$1
N$35
  Top 0.406: 9+1.P$1 135.13,90.17 126.49,83.82 126.49,88.9 122.68,91.95 112.27,91.95 21+1.P$2
N$36
  Top 0.406: 21+1.P$1 22+1.P$2
N$37
  Top 0.406: 22+1.P$1 123.19,81.53 115.32,75.44 115.32,78.99 109.73,78.99 23+1.P$2
N$38
  Top 0.61: +1+1.P$2 78.74,72.39 85.6,74.68 25+1.P$1
N$39
  Top 0.61: 25+1.P$2 83.82,81.79 90.93,81.79 91.69,85.85 97.54,85.85 24+1.P$1
N$40
  Top 0.61: 24+1.P$2 95.25,80.01 108.2,71.88 110.74,71.88 112.78,73.66 23+1.P$1
N$41
  Top 0.61: 2+1.P$2 139.19,36.32 arc-19 7+1.P$1
N$42
  Top 0.61: 7+1.P$2 118.65,22.07 114.61,34.64 27+1.P$1
N$43
  Top 0.406: 8+1.P$1 9+1.P$2
N$44
  pour Top (isolate 0.813, hatched): 76.73,152.45 arc-78 150.27,90.47 arc-83 103.84,5.31 arc-84 9.42,40.97 arc-114 75.54,152.35 74.55,145.8 arc110 15.49,44.2 arc241 76.73,145.82
N$45  (via drill 0.6)
  Top 0.406: +20+3.P$2 40.89,43.6 40.89,45.21 42.53,46.85 R17.1 48.37,46.85 50.8,49.28 53.85,49.28 v55.12,50.55 | v67.06,65.79 70.61,65.79 71.37,65.02 72.02,65.02 R19.2 74.03,65.39 75.18,66.55 R14.2
  Bottom 0.406: v55.12,50.55 55.37,50.55 56.39,53.09 56.39,59.18 62.74,64.26 64.77,65.79 v67.06,65.79
N$46
  Top 0.61: +19+2.P$2 69.34,89.92 +20+2.P$1
N$47
  Top 0.61: +19+2.P$1 76.2,103.12 74.68,105.16 28+2.P$2
N$48
  Top 0.61: 27+2.P$2 59.18,94.74 64.77,94.74 69.09,102.87 71.12,111.25 72.39,115.32 73.15,117.6 77.72,117.6 28+2.P$1
N$49
  Top 0.61: 4+2.P$2 33.02,128.27 arc-34 74.17,146.07 69.85,132.33 72.39,132.33 2+2.P$1
N$50
  Top 0.61: 4+2.P$1 34.54,137.41 arc-20 43.18,143 6+2.P$2
N$51
  Top 0.61: 6+2.P$1 49.28,145.03 arc-23 57.4,148.08 0+2.P$2
N$52
  Top 0.61: 0+2.P$1 64.52,149.35 arc-20 72.9,150.11 5+2.P$2
N$53
  Top 0.61: 5+2.P$1 78.99,149.1 79.5,149.86 arc-21 88.39,149.1 3+2.P$2
N$54
  Top 0.61: 3+2.P$1 94.49,148.34 arc-17 103.38,145.03 1+2.P$2
N$55
  Top 0.61: 1+2.P$1 109.73,142.24 arc-29 116.59,138.18 8+2.P$2
N$56
  Top 0.61: 21+2.P$2 84.69,125.99 81.92,134.17 9+2.P$1
N$57
  Top 0.61: 22+2.P$2 88.39,114.55 86.36,120.65 21+2.P$1
N$58
  Top 0.61: 23+2.P$2 92.65,101.33 89.82,110.06 22+2.P$1
N$59
  Top 0.61: +1+2.P$2 75.69,88.14 81.03,88.14 81.79,86.87 86.87,86.87 +2+2.P$1
N$60
  Top 0.61: +2+2.P$2 86.11,94.23 106.68,94.23 24+2.P$1
N$61
  Top 0.61: 23+2.P$1 94.68,99.67 102.75,99.67 24+2.P$2
N$62
  Top 0.61: 2+2.P$2 64.77,117.09 7+2.P$1
N$63
  Top 0.61: 7+2.P$2 63.5,113.03 60.2,101.85 62.23,98.04 27+2.P$1
N$64
  Top 0.61: 9+2.P$2 77.98,137.92 80.37,138.97 78.49,145.29 77.98,145.8 arc-37 117.35,132.08 120.4,133.86 8+2.P$1
N$65
  Top 0.406: +20+2.P$2 64.91,89.18 R15.1 64.49,87.26 R18.2
N$66
  Top 0.406: R8.1 45.21,55.49 +20.P$2 45.83,57.88 R20.2
N$67
  Top 0.406: 43.94,40.64 +20+3.P$1
  Top 0.61: +19+3.P$2 39.88,40.64 43.94,40.64
N$68
  Top 0.61: 28+3.P$2 23.88,22.86 28.7,18.8 32,21.84 33.78,21.84 35.56,27.69 39.12,27.69 +19+3.P$1
N$69
  Top 0.61: 27+3.P$2 arc14 18.54,29.72 23.37,29.72 28+3.P$1
N$70
  Top 0.61: 4+3.P$2 arc9 2.03,71.12 4.83,71.12 4.83,69.85 2+3.P$1
N$71
  Top 0.61: 6+3.P$2 arc14 2.79,87.12 5.08,86.61 4+3.P$1
N$72
  Top 0.61: 0+3.P$2 arc10 6.35,101.85 8.64,101.09 6+3.P$1
N$73
  Top 0.61: 0+3.P$1 14.73,115.57 12.95,115.57 arc-12 5+3.P$2
N$74
  Top 0.61: 5+3.P$1 26.16,121.41 arc21 13.46,99.57 17.78,99.57 18.78,98.82 18.54,98.81 18.78,98.03 3+3.P$2
N$75
  Top 0.61: 1+3.P$2 3+3.P$1
N$76
  Top 0.61: 8+3.P$2 33.78,77.47 25.4,84.07 25.4,87.12 1+3.P$1
N$77
  Top 0.61: 21+3.P$2 31.69,96.84 31.75,96.77 34.04,92.71 39.88,91.95 43.18,90.42 9+3.P$1
N$78
  Top 0.61: 21+3.P$1 38.1,99.57 42.93,99.57 22+3.P$2
N$79
  Top 0.61: 23+3.P$2 22+3.P$1
N$80
  Top 0.61: +1+3.P$2 61.98,74.17 +2+3.P$1
N$81
  Top 0.61: +3+3.P$1 +2+3.P$2
N$82
  Top 0.61: +3+3.P$2 49.28,75.18 57.4,78.99 23+3.P$1
N$83
  Top 0.61: 2+3.P$2 arc22 4.83,56.39 7.62,56.39 7.87,55.12 7+3.P$1
N$84
  Top 0.61: 7+3.P$2 arc23 10.41,42.42 13.97,42.42 27+3.P$1
N$85
  Top 0.61: 9+3.P$2 39.62,80.26 8+3.P$1
N$86  (3 unrouted)
  Bottom 0.61: U$1.P$8 84.41,42.93 P4ZD1.C 84.71,42.55 C5.2
N$87
  Bottom 0.61: R4.1 70.76,60.35 70.87,64.77 76.71,64.77 76.71,63.3 OK1.1
N$88  (1 unrouted)
  Bottom 0.406: U$2.1 74.17,50.29 U$1.P$5
  Bottom 0.61: R1.1 90.69,48.41 PH1.2 89.31,47.91 89.15,47.75 85.6,51.82 84.58,52.83 81.28,50.04 80.77,50.55 U$1.P$5
N$89  (1 unrouted)
N$90  (1 unrouted)
N$91  (3 unrouted)
  Bottom 0.813: B2.+ D4.C D3.C
N$92  (1 unrouted)
N$93  (6 unrouted)
  Bottom 0.813: D6.A B2.- 97.28,83.82 D5.A
N$94  (2 unrouted)
  Bottom 0.61: OK1.4 82.37,68.91 82.8,70.61 82.8,81.81 R13.2
N$95  (1 unrouted)
  Bottom 0.406: U$2.4 72.14,37.08 61.47,37.08 61.47,48.01 U$1.P$3
N$96  (2 unrouted)
N$97  (2 unrouted)
N$98  (1 unrouted)
  Bottom 0.813: R28.2 105.03,111.38 103.89,112.52 arc36 70.36,121.16 JP3.P$1
N$99  (1 unrouted)
N$100  (1 unrouted)
N$101  (3 unrouted)
  Bottom 0.406: C2.+ 50.29,82.8 52.07,81.03 52.07,77.98 51.82,77.72 51.82,77.52 C9.+
N$102  (2 unrouted)
  Bottom 0.406: U$2.3 76.71,42.42 76.96,35.56 64.77,35.56 59.18,35.81 59.18,50.55 U$1.P$4
N$103  (1 unrouted)
N$104  (2 unrouted)
N$105  (1 unrouted)
N$106  (1 unrouted)
  Bottom 0.813: D8.C 101.35,105.66 96.27,113.28 JP4.P$1
N$107  (1 unrouted)
N$108  (1 unrouted)
RECDR+  (4 unrouted)
  Bottom 0.61: R10.P$1 B1.+
VDD  (7 unrouted)
  Bottom 0.406: U$1.P$2 U$2.5
VSS  (10 unrouted)
  Bottom 0.406: C9.- 45.51,81.33 C2.- | U$2.2 U$1.P$7
  Bottom 0.61: OK1.2 74.17,63.05 74.17,60.2 75.69,59.18 76.45,56.39 77.72,55.88 92.46,55.88 95.76,51.56 95.76,46.99 94.49,45.72 92.73,45.72 R1.2 92.58,43.31 91.69,42.42 87.93,42.42 P4ZD1.A 87.51,42.24 C5.1
(copper drawn outside any net)
  shapes: Bottom circle x2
